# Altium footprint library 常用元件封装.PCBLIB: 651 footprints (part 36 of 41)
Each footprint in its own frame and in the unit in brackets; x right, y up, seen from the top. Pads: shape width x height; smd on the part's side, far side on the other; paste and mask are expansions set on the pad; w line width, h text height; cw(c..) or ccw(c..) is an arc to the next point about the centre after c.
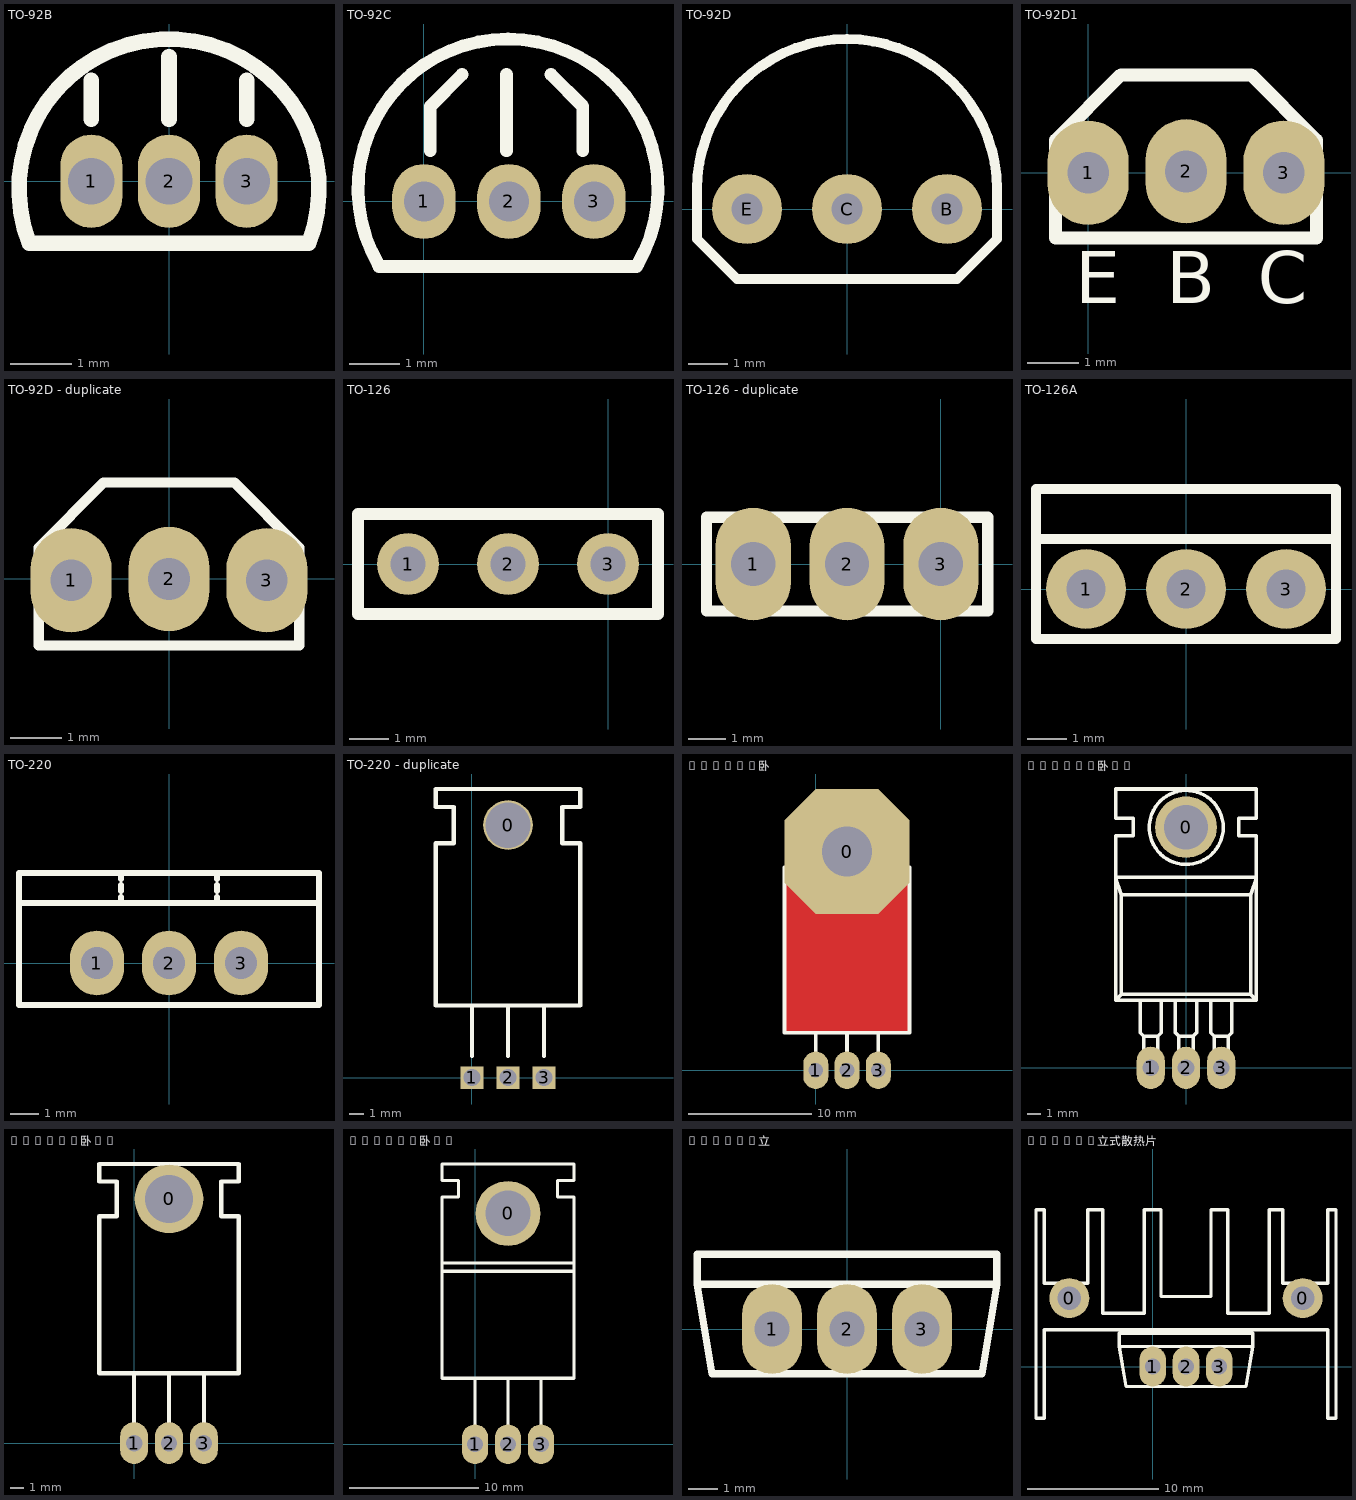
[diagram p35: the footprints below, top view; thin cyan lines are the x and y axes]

## TO-92B [mil]
pads (3):
  oval 40x60 hole 30: 1(-50,0) 2(0,0) 3(50,0)
TopOverlay:
  lines w9.84: -90,-40 90,-40
  lines w10: -90,-40 cw(c0,-5) 90,-40 ; -50,40 -50,65 ; 0,40 0,80 ; 50,40 50,65

## TO-92C [mm]
pads (3):
  oval 1.27x1.5 hole 0.8: 1(0,0) 2(1.7,0) 3(3.4,0)
TopOverlay:
  lines w0.254: -0.918,-1.25 cw(c1.68,0.25) 4.278,-1.25 ; -0.9,-1.3 4.25,-1.3 ; 0.127,1.016 0.127,1.905 0.762,2.54 ; 1.651,1.016 1.651,2.54 ; 2.54,2.54 3.175,1.905 3.175,1.016

## TO-92D [mil]
pads (3):
  round 70 hole 31.5: B(100,0) C(0,0) E(-100,0)
TopOverlay:
  lines w10: -150,-30 -150,20 cw(c0,20) 150,20 150,-30 110,-70 -110,-70 -150,-30

## TO-92D1 [mil]
pads (3):
  oval 62x80 hole 32: 1(0,0) 2(75,1) 3(150,0)
TopOverlay:
  lines w10: -25,-50 175,-50 175,25 125,75 25,75 -25,25 -25,-50
  text "C" at 130,-100 h40
  text "B" at 60,-100 h40
  text "E" at -10,-100 h40

## TO-92D - duplicate [mil]
pads (3):
  oval 62x80 hole 32: 1(-75,-1) 2(0,0) 3(75,-1)
TopOverlay:
  lines w8: -100,-51 -100,24 -50,74 50,74 100,24 100,-51 -100,-51

## TO-126 [mil]
pads (3):
  round 62 hole 35.43: 1(-200,0) 2(-100,0) 3(0,0)
TopOverlay:
  lines w12: -250,-50 50,-50 50,50 -250,50 -250,-50

## TO-126 - duplicate [mil]
pads (3):
  oval 80x120 hole 47.24: 1(-200,0) 2(-100,0) 3(0,0)
TopOverlay:
  lines w12: -250,-50 -250,50 50,50 50,-50 -250,-50

## TO-126A [mil]
pads (3):
  round 80 hole 39: 1(-100,0) 2(0,0) 3(100,0)
TopOverlay:
  lines w10: 150,40 150,100 -150,100 -150,50 ; -150,50 -150,-50 150,-50 150,50 -150,50

## TO-220 [mil]
pads (3):
  oval 75x90 hole 45: 1(-100,0) 2(0,0) 3(100,0)
TopOverlay:
  lines w7.87: -66.67,83.33 -66.67,91.67 ; -66.67,100 -66.67,108.33 ; -66.67,116.67 -66.67,125 ; 66.67,83.33 66.67,91.67 ; 66.67,100 66.67,108.33 ; 66.67,116.67 66.67,125 ; -208.33,83.33 208.33,83.33 ; -208.33,83.33 -208.33,-58.33 208.33,-58.33 208.33,83.33 ; -208.33,83.33 -208.33,125 208.33,125 208.33,83.33

## TO-220 - duplicate [mm]
pads (4):
  round 3.5 hole 3.2: 0(2.54,17.78)
  rect 1.6x1.6 hole 1.2: 1(0,0) 2(2.54,0) 3(5.08,0)
TopOverlay:
  lines w0.305: 0,1.524 0,5.08 ; 2.54,1.524 2.54,5.08 ; 5.08,1.524 5.08,5.08 ; -2.54,5.08 7.62,5.08 7.62,16.51 6.35,16.51 6.35,19.05 7.62,19.05 7.62,20.32 -2.54,20.32 -2.54,19.05 -1.27,19.05 -1.27,16.51 -2.54,16.51 -2.54,5.08

## TO-220卧 [mil]
pads (4):
  oct 400x400 hole 160: 0(100,700)
  oval 80x120 hole 47.24: 1(0,0) 2(100,0) 3(200,0)
TopLayer:
  rectangle: -99,126 297,800
TopOverlay:
  lines w12: -100,650 -100,120 300,120 300,650 ; 0,60 0,120 ; 100,60 100,120 ; 200,60 200,120

## TO-220卧-1 [mil]
pads (4):
  round 175 hole 125.98: 0(0,683.33)
  oval 80x120 hole 47.24: 1(-100,0) 2(0,0) 3(100,0)
TopOverlay:
  circle w10: c0.67,682.53 r105
  lines w10: -130,191.67 -130,100 -120,90 ; -70,191.67 -70,100 -80,90 ; -30,191.67 -30,100 -20,90 ; 30,191.67 30,100 20,90 ; 70,191.67 70,100 80,90 ; 130,191.67 130,100 120,90 ; -200,191.67 -183.33,208.33 ; -200,191.67 200,191.67 ; -200,191.67 -200,658.33 -150,658.33 -150,708.33 -200,708.33 -200,791.67 200,791.67 200,708.33 150,708.33 150,658.33 200,658.33 200,191.67 ; -183.33,208.33 183.33,208.33 ; -183.33,208.33 -183.33,491.67 ; -183.33,491.67 183.33,491.67 ; -183.33,491.67 -200,541.67 200,541.67 183.33,491.67 ; -120,90 -80,90 ; -120,90 -120,50 -80,50 -80,90 ; -20,90 20,90 ; -20,90 -20,50 20,50 20,90 ; 80,90 120,90 ; 80,90 80,50 120,50 120,90 ; 183.33,208.33 200,191.67 ; 183.33,208.33 183.33,491.67

## TO-220卧-2 [mil]
pads (4):
  round 196.85 hole 137.8: 0(100,700)
  oval 80x120 hole 47.24: 1(0,0) 2(100,0) 3(200,0)
TopOverlay:
  lines w12: 0,60 0,200 ; 100,60 100,200 ; 200,60 200,200 ; -100,200 -100,650 -50,650 -50,750 -100,750 -100,800 300,800 300,750 250,750 250,650 300,650 300,200 -100,200

## TO-220卧-3 [mil]
pads (4):
  round 196.85 hole 137.8: 0(100,700)
  oval 80x120 hole 47.24: 1(0,0) 2(100,0) 3(200,0)
TopOverlay:
  lines w10: -100,525 300,525 ; 0,50 0,200 ; 100,50 100,200 ; 200,50 200,200 ; -100,550 -100,200 300,200 300,550 ; -100,550 -100,750 -50,750 -50,800 -100,800 -100,850 300,850 300,800 250,800 250,750 300,750 300,550 ; -100,550 300,550

## TO-220立 [mil]
pads (3):
  oval 80x120 hole 47.24: 1(-100,0) 2(0,0) 3(100,0)
TopOverlay:
  lines w10: -200,60 -200,100 200,100 200,60 ; -200,60 -180,-60 180,-60 200,60 ; -200,60 200,60

## TO-220立式散热片 [mil] "焊孔17.9mm  23mmX16mm"
height 984.25
pads (5):
  round 120 hole 70: 0(-250,205) 0(450,205)
  oval 80x120 hole 47.24: 1(0,0) 2(100,0) 3(200,0)
TopOverlay:
  lines w10: -100,60 -100,100 300,100 300,60 ; -100,60 -80,-60 280,-60 300,60 ; -100,60 300,60 ; -350,-155 -350,470 -325,470 -325,250 -195,250 -195,470 -150,470 -150,160 -25,160 -25,470 25,470 25,210 175,210 175,470 225,470 225,160 350,160 350,470 390,470 390,250 525,250 525,470 550,470 550,-155 525,-155 525,110 -325,110 -325,-155 -350,-155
